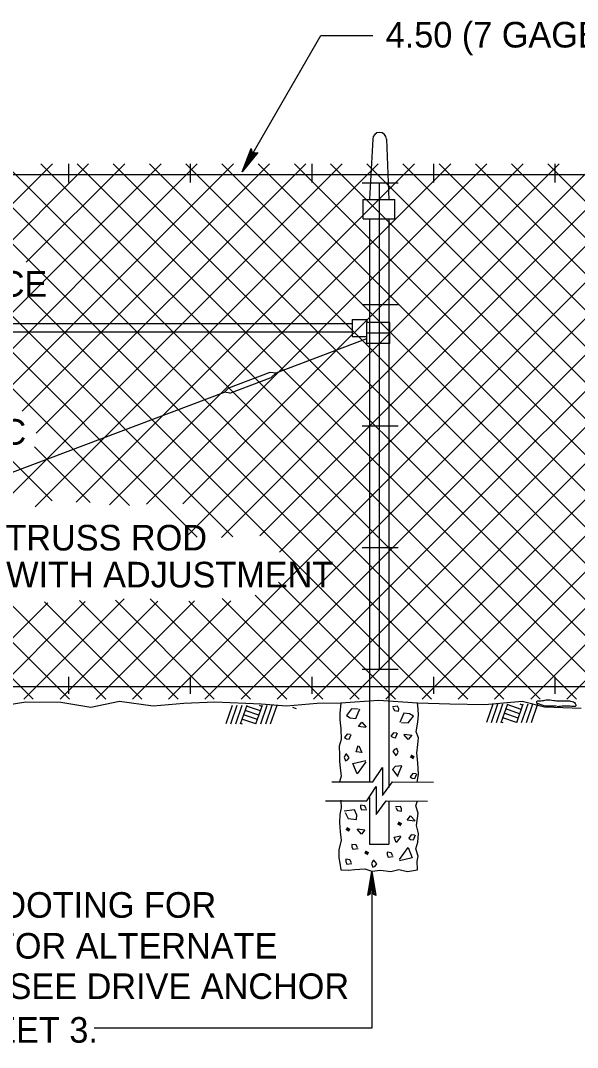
# Model space of a CAD drawing. Extents: x 13 to 918, y -903 to 879.
# Drawn here: x 195.1 to 263, y -24.7 to 100.7 of the extents above; entities that cross this region are included whole.
import ezdxf

# ---------------------------------------------------------------- set-up
doc = ezdxf.new("R2010")
doc.units = 0
for name, color, linetype in [('1', 7, 'Continuous'), ('2', 7, 'Continuous'), ('3', 7, 'Continuous')]:
    doc.layers.add(name, color=color, linetype=linetype)

msp = doc.modelspace()

# ---------------------------------------------------------------- linework, layer by layer
at = {"layer": '1'}
for p, q in [((220.883, 17.0405), (220.11, 14.8135)), ((221.47875, 17.0405), (220.69125, 14.77175)), ((222.0745, 17.0405), (221.287, 14.77175)), ((222.6705, 17.0405), (221.883, 14.77175)), ((224.16425, 15.86775), (222.46825, 16.45725)), ((224.3475, 16.399), (222.65175, 16.9865)), ((224.55175, 17.0405), (223.76625, 14.77175)), ((224.53075, 16.93025), (224.21625, 17.0405)), ((225.1475, 17.0405), (224.362, 14.77175)), ((225.74125, 17.0405), (224.958, 14.77175)), ((226.33925, 17.0405), (225.55375, 14.77175)), ((228.74125, 16.64275), (228.287, 16.803)), ((252.70575, 17.2135), (251.933, 14.9865)), ((253.30175, 17.2135), (252.51425, 14.94475)), ((253.8975, 17.2135), (253.11, 14.94475)), ((254.49325, 17.2135), (253.70575, 14.94475)), ((255.987, 16.0405), (254.29125, 16.63025)), ((256.1705, 16.57175), (254.4745, 17.15925)), ((256.3745, 17.2135), (255.58925, 14.94475)), ((256.35375, 17.103), (256.03925, 17.2135)), ((256.9705, 17.2135), (256.185, 14.94475)), ((257.56425, 17.2135), (256.78075, 14.94475)), ((258.162, 17.2135), (257.37675, 14.94475)), ((223.7955, 14.80525), (222.0975, 15.3905)), ((223.98075, 15.3365), (222.283, 15.92175)), ((255.61825, 14.978), (253.9205, 15.5635)), ((255.80375, 15.50925), (254.10575, 16.09475)), ((222.162, 14.77175), (221.91425, 14.85925)), ((253.985, 14.94475), (253.737, 15.03225))]:
    msp.add_line(p, q, dxfattribs=at)
at = {"layer": '2'}
for p, q in [((222.12875, 82.199), (231.735, 98.83425)), ((231.735, 98.83425), (238.0495, 98.83425)), ((238.0495, 86.1635), (237.67875, 78.8365)), ((239.72875, 86.1635), (240.02875, 78.75925)), ((200.96625, 80.878), (200.96625, 83.18225)), ((215.81, 80.878), (215.81, 83.18225)), ((230.65575, 80.878), (230.65575, 83.18225)), ((245.50175, 80.878), (245.50175, 83.18225)), ((260.3455, 80.878), (260.3455, 83.18225)), ((129.09125, 81.88225), (573.9705, 81.88225)), ((236.7705, 80.85925), (241.16, 80.85925)), ((238.85375, 80.85925), (238.85375, 21.351)), ((236.8955, 78.80725), (240.7495, 78.80725)), ((236.8955, 76.4615), (236.8955, 78.80725)), ((240.7495, 76.4615), (240.7495, 78.80725)), ((236.8955, 76.4615), (240.7495, 76.4615)), ((237.67875, 76.4615), (237.67875, 7.6865)), ((240.02875, 76.4615), (240.02875, 7.05525)), ((236.7705, 66.0135), (241.16, 66.0135)), ((235.562, 64.174), (237.3475, 64.174)), ((235.562, 64.174), (235.562, 62.0905)), ((237.3475, 64.174), (237.3475, 63.78225)), ((235.562, 63.653), (132.05175, 63.653)), ((240.13925, 63.78225), (237.3475, 63.78225)), ((237.3475, 62.48225), (237.3475, 63.78225)), ((237.3475, 63.13225), (237.3475, 63.13225)), ((237.3475, 63.13225), (237.3475, 63.13225)), ((238.85375, 63.13225), (238.85375, 63.13225)), ((238.85375, 63.13225), (238.85375, 63.13225)), ((240.13925, 61.22175), (240.13925, 63.78225)), ((235.562, 62.6115), (132.05175, 62.6115)), ((226.28075, 57.674), (237.3475, 61.853)), ((235.562, 62.0905), (237.3475, 62.0905)), ((240.13925, 62.48225), (237.3475, 62.48225)), ((237.3475, 61.22175), (237.3475, 62.48225)), ((240.13925, 61.22175), (237.3475, 61.22175)), ((220.47875, 55.83225), (225.52675, 57.7365)), ((225.52675, 57.7365), (226.28075, 57.674)), ((226.28075, 57.674), (225.662, 57.09275)), ((220.60175, 55.18225), (225.662, 57.09275)), ((128.07675, 20.59675), (219.94325, 55.28225)), ((219.94325, 55.28225), (220.47875, 55.83225)), ((220.60175, 55.18225), (219.94325, 55.28225)), ((236.7705, 51.16975), (241.16, 51.16975)), ((236.7705, 36.324), (241.16, 36.324)), ((236.7705, 21.48025), (241.16, 21.48025)), ((200.96625, 18.46975), (200.96625, 20.549)), ((215.81, 18.46975), (215.81, 20.549)), ((230.65575, 18.46975), (230.65575, 20.549)), ((245.50175, 18.46975), (245.50175, 20.549)), ((260.3455, 18.46975), (260.3455, 20.549)), ((129.09125, 19.38225), (573.912, 19.38225)), ((234.158, 17.29675), (234.158, 17.29675)), ((238.85375, 17.29675), (238.85375, 17.29675)), ((243.5475, 17.29675), (243.5475, 17.29675)), ((261.237, 17.29675), (261.237, 17.29675)), ((237.67875, 5.83425), (237.67875, 0.10925)), ((240.02875, 5.35725), (240.02875, 0.10925)), ((237.67875, 0.10925), (240.02875, 0.10925)), ((237.95375, -3.174), (237.95375, -22.317)), ((238.85375, -3.04075), (238.85375, -3.04075)), ((237.95375, -22.317), (204.05639, -22.317))]:
    msp.add_line(p, q, dxfattribs=at)
for points in [[(182.32875, 53.29275), (212.21825, 83.18225)], [(249.65575, 17.81775), (184.29125, 83.18225)], [(186.658, 70.88225), (198.958, 83.18225)], [(186.7455, 53.29275), (216.635, 83.18225)], [(254.07675, 17.81775), (188.712, 83.18225)], [(190.88475, 39.75275), (234.31425, 83.18225)], [(191.03925, 53.16575), (221.05575, 83.18225)], [(191.362, 71.1655), (203.37875, 83.18225)], [(258.4975, 17.81775), (193.133, 83.18225)], [(195.2675, 52.97525), (225.4745, 83.18225)], [(195.758, 71.14275), (207.7955, 83.18025)], [(196.8495, 41.299), (238.733, 83.18225)], [(196.9925, 50.2815), (229.89325, 83.18225)], [(262.91425, 17.81775), (197.5495, 83.18225)], [(201.8495, 41.878), (243.15375, 83.18225)], [(267.335, 17.81775), (201.9705, 83.18225)], [(205.93925, 41.549), (247.5725, 83.18225)], [(271.75375, 17.81775), (206.38925, 83.18225)], [(210.44125, 41.63225), (251.98925, 83.18025)], [(276.1725, 17.81775), (210.808, 83.18225)], [(213.14125, 17.81775), (278.50575, 83.18225)], [(214.8955, 41.66775), (256.408, 83.18025)], [(280.59325, 17.81775), (215.22875, 83.18225)], [(215.262, 37.6155), (260.82875, 83.18225)], [(217.56425, 17.81775), (282.92875, 83.18225)], [(219.612, 37.54475), (265.2475, 83.18025)], [(285.01425, 17.81775), (219.6495, 83.18225)], [(221.983, 17.81775), (287.3475, 83.18225)], [(289.433, 17.81775), (224.06825, 83.18225)], [(224.258, 37.77175), (269.66825, 83.18225)], [(226.40375, 17.81775), (291.76825, 83.18225)], [(226.66825, 35.7615), (274.08925, 83.18225)], [(293.85175, 17.81775), (228.487, 83.18225)], [(230.8205, 17.81775), (296.185, 83.18225)], [(298.2725, 17.81775), (232.908, 83.18225)], [(235.24125, 17.81775), (300.60575, 83.18225)], [(302.69125, 17.81775), (237.32675, 83.18225)], [(239.658, 17.81775), (305.0225, 83.18225)], [(307.11, 17.81775), (241.7455, 83.18225)], [(244.07875, 17.81775), (309.44325, 83.18225)], [(307.1925, 22.154), (246.16425, 83.18225)], [(248.4975, 17.81775), (313.862, 83.18225)], [(303.372, 30.393), (250.583, 83.18225)], [(252.9205, 17.81775), (318.283, 83.18025)], [(306.42, 31.766), (255.00375, 83.18225)], [(257.337, 17.81775), (322.70175, 83.18225)], [(310.83625, 31.766), (259.4205, 83.18225)], [(245.237, 17.81775), (195.985, 67.06975)], [(208.35575, 41.44275), (184.5725, 65.228)], [(216.637, 37.58025), (189.083, 65.13425)], [(220.985, 37.651), (193.4705, 65.16775)], [(198.91, 42.04675), (193.0475, 47.90925)], [(203.55575, 41.81975), (196.751, 48.62475)], [(196.6245, 17.81775), (166.86625, 47.576)], [(201.04325, 17.81775), (171.285, 47.576)], [(205.462, 17.81775), (175.70375, 47.576)], [(261.758, 17.81775), (288.0455, 44.10525)], [(240.81825, 17.81775), (226.5475, 32.0885)], [(231.98075, 17.81775), (219.69325, 30.10525)], [(236.3995, 17.81775), (223.6975, 30.52175)], [(186.62675, 17.81775), (198.40575, 29.59675)], [(191.0455, 17.81775), (202.95375, 29.726)], [(195.46425, 17.81775), (207.70575, 30.05925)], [(209.883, 17.81775), (197.9995, 29.703)], [(199.885, 17.81775), (211.84325, 29.776)], [(214.30375, 17.81775), (202.25175, 29.87175)], [(204.30375, 17.81775), (216.2975, 29.8115)], [(218.7205, 17.81775), (206.6475, 29.89275)], [(208.7245, 17.81775), (220.75175, 29.84475)], [(223.13925, 17.81775), (210.8995, 30.05925)], [(227.56, 17.81775), (215.59325, 29.78425)], [(193.1995, 17.09475), (195.6995, 17.5155), (199.9745, 17.4385), (203.63925, 16.84675), (207.1495, 17.5905), (211.25375, 17.01775), (215.01425, 17.34275), (218.7725, 17.5155), (224.44125, 17.26775), (227.533, 17.01775), (231.29325, 17.34275), (234.16625, 17.38025), (238.7745, 17.6865), (243.54125, 17.38025), (247.458, 17.26775), (251.733, 17.17175), (256.31425, 17.5905), (259.00575, 16.903), (263.51, 16.73225)], [(234.16625, 17.38025), (234.0225, 16.08425), (234.0225, 15.301), (234.1745, 14.19475), (234.21425, 12.89675), (233.9455, 12.076), (233.985, 11.026), (233.985, 10.224), (234.0995, 9.44275), (234.21425, 8.43025), (234.00175, 7.7385)], [(236.2975, 16.599), (235.46825, 16.653), (234.84325, 15.8405), (235.3225, 15.54475), (235.985, 15.453), (236.4975, 16.628)], [(240.52675, 16.799), (240.708, 16.428), (241.21825, 16.35525), (241.22675, 16.6365), (241.0975, 16.951), (240.462, 16.878)], [(243.49325, 7.65525), (243.64125, 8.65925), (243.56425, 10.03425), (243.4495, 11.2155), (243.56425, 12.30525), (243.64125, 13.10525), (243.3745, 13.851), (243.56425, 15.03425), (243.64125, 15.89275), (243.60375, 16.599), (243.54125, 17.38025)], [(241.562, 14.99275), (242.387, 14.9385), (243.01625, 15.74675), (242.537, 16.04275), (241.86625, 16.13425), (241.35375, 14.9635)], [(237.20575, 14.378), (236.31, 14.478), (236.73075, 15.00725), (237.2725, 14.41775)], [(235.32875, 13.51775), (234.91625, 13.54475), (234.60175, 13.1385), (234.84125, 12.9905), (235.17675, 12.94675), (235.43075, 13.53025)], [(240.987, 13.69275), (240.5745, 13.71975), (240.26, 13.3135), (240.4995, 13.1655), (240.835, 13.12175), (241.08925, 13.70525)], [(241.9205, 13.54275), (242.81825, 13.44275), (242.3975, 12.9135), (241.85375, 13.503)], [(236.36, 12.14275), (236.7225, 11.3155), (236.05375, 11.4155), (236.29325, 12.18025)], [(240.94325, 11.001), (241.1745, 11.34475), (240.98075, 11.81975), (240.733, 11.6865), (240.5245, 11.41975), (240.90375, 10.90525)], [(234.77875, 11.099), (234.5495, 10.75525), (234.74125, 10.278), (234.98925, 10.4115), (235.1975, 10.68025), (234.81625, 11.19475)], [(237.21, 10.18025), (236.13925, 8.726), (235.64325, 9.98425), (237.20575, 10.33425)], [(233.0495, 7.74275), (238.08925, 7.724), (239.25175, 9.478), (239.25175, 6.0635), (240.4745, 7.724), (245.49325, 7.703)], [(241.0995, 8.426), (241.60375, 9.68425), (240.80375, 9.62175), (240.45375, 9.24275), (241.1245, 8.3885)], [(243.3475, 8.70925), (242.935, 8.7365), (242.6205, 8.33025), (242.86, 8.18225), (243.1955, 8.1385), (243.4495, 8.72175)], [(232.285, 5.4155), (237.3245, 5.39675), (238.487, 7.151), (238.487, 3.7365), (239.71, 5.39675), (244.72875, 5.376)], [(234.1725, 5.4865), (234.1745, 5.47175), (234.21425, 4.574), (234.0225, 3.75525), (233.985, 2.7615), (234.0995, 1.61775), (234.21425, 0.60525), (233.908, -0.57825), (233.908, -1.551), (234.0225, -2.18025), (234.16625, -3.01575), (235.11, -3.0595), (235.8745, -2.98225), (237.07675, -2.8865), (237.95375, -3.174), (239.00375, -3.0595), (240.26425, -3.2115), (241.25575, -2.98225), (242.30575, -3.2115), (243.54125, -3.01575), (243.48925, -1.95325), (243.60375, -1.322), (243.335, -0.4635), (243.56425, 0.35725), (243.64125, 1.426), (243.412, 2.41775), (243.60375, 3.90725), (243.335, 4.803), (243.52675, 5.39475), (243.52675, 5.4155)], [(234.70175, 4.003), (235.06825, 3.2615), (236.085, 3.11975), (236.10175, 3.68225), (235.84325, 4.3115), (234.5725, 4.1655)], [(237.2725, 4.453), (237.08925, 4.824), (236.58075, 4.89275), (236.5725, 4.6115), (236.70175, 4.299), (237.335, 4.36975)], [(240.887, 4.5885), (241.0705, 4.21775), (241.57875, 4.14475), (241.587, 4.426), (241.458, 4.74275), (240.8225, 4.66975)], [(243.158, 2.9365), (242.262, 3.0365), (242.683, 3.5655), (243.2245, 2.976)], [(236.212, 1.9865), (237.11, 1.8865), (236.68925, 1.35725), (236.1455, 1.94675)], [(243.1725, 1.23425), (242.76, 1.2615), (242.4455, 0.85525), (242.685, 0.70725), (243.0205, 0.6635), (243.2745, 1.24675)], [(236.208, -0.34075), (236.0245, 0.03025), (235.51625, 0.099), (235.508, -0.18225), (235.635, -0.49275), (236.2705, -0.422)], [(241.46825, 1.0655), (240.933, 0.3405), (240.685, 0.96975), (241.46625, 1.14275)], [(240.50375, -1.29475), (240.3205, -0.924), (239.812, -0.85525), (239.80375, -1.1365), (239.93075, -1.447), (240.56625, -1.376)], [(241.3225, -1.751), (242.39325, -0.301), (242.88925, -1.5595), (241.3225, -1.90525)], [(235.462, -2.15725), (235.27875, -1.7845), (234.7705, -1.71575), (234.762, -1.997), (234.88925, -2.3095), (235.5245, -2.2385)], [(238.12675, -1.872), (237.8975, -2.21575), (238.08925, -2.69275), (238.337, -2.5595), (238.5455, -2.29075), (238.16425, -1.776)]]:
    msp.add_lwpolyline(points, dxfattribs=at)
msp.add_arc((238.88922, 86.16354), 0.83958, 0, 180, dxfattribs=at)
msp.add_spline([(260.4745, 16.9615), (259.69125, 16.9615), (258.985, 16.999), (258.508, 17.1905), (258.108, 17.34275), (258.0705, 17.53425), (258.6225, 17.63025), (259.21425, 17.74475), (260.1495, 17.66775), (260.837, 17.63025), (261.658, 17.63025), (262.212, 17.5905), (262.55575, 17.49475), (262.76425, 17.30525), (262.84125, 16.999), (262.1725, 16.9615), (261.6205, 16.9615), (261.41, 16.9615), (260.55175, 16.903)], degree=3, dxfattribs=at)
at = {"layer": '3'}
for points in [[(223.85575, 84.478), (223.6245, 84.4905), (222.12875, 82.199), (223.85575, 84.478), (224.037, 84.54275), (222.12875, 82.199), (223.37675, 84.63025), (223.25175, 84.81775), (222.12875, 82.199), (223.21, 85.01975), (223.25175, 84.81775)], [(237.5975, -6.0115), (237.80375, -5.90525), (237.95375, -3.174), (237.5975, -6.0115), (237.4725, -6.15725), (237.95375, -3.174), (238.08925, -5.903), (238.29125, -6.003), (237.95375, -3.174), (238.42875, -6.15725), (238.29125, -6.003)]]:
    msp.add_lwpolyline(points, dxfattribs=at)

# ---------------------------------------------------------------- texts
at = {"layer": '2'}
for p in [(242.808, 10.15925), (241.258, 1.9865), (234.958, 1.30525), (237.237, -1.55525)]:
    msp.add_text('.', height=3.125, rotation=60, dxfattribs=at).set_placement(p)
at = {"layer": '3'}
for s, height, p in [('4.50 (7 GAGE ) THICK TENSION WIRE', 3.1249995, (239.64125, 97.3635)), ('BRACE', 3.124999, (183.933, 66.949)), ('CLAMPS AT 355 (14") C TO C', 3.1249995, (138.54175, 48.8785)), ('TRUSS ROD', 3.124999, (193.21825, 35.97175)), ('WITH ADJUSTMENT', 3.1249995, (193.31425, 31.4635)), ('CONCRETE FOOTING FOR', 3.1249995, (165.32875, -8.85725)), ('ALL POSTS.  FOR ALTERNATE', 3.1249995, (165.57675, -13.84475)), ('ANCHORING, SEE DRIVE ANCHOR', 3.1249995, (165.7495, -18.774)), ('DETAILS, SHEET 3.', 3.1249995, (166.19125, -24.10725))]:
    msp.add_text(s, height=height, dxfattribs=at).set_placement(p)

doc.saveas('drawing.dxf')
